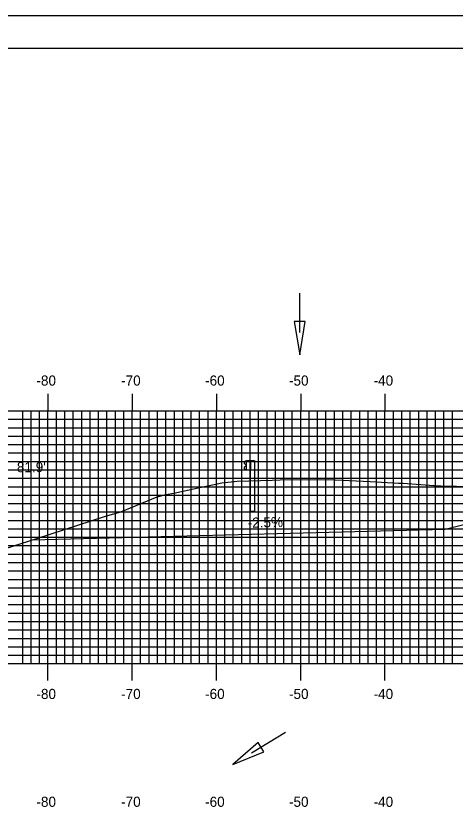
# Model space of a CAD drawing. Extents: x 1684405 to 1684749, y 461260 to 461480.
# Drawn here: x 1684487.4 to 1684539.5, y 461385.6 to 461480 of the extents above; entities that cross this region are included whole.
import ezdxf

# ---------------------------------------------------------------- set-up
doc = ezdxf.new("R2010")
doc.units = 0
for name, color, linetype in [('ANNOTATION', 7, 'Continuous'), ('BORDER', 7, 'Continuous'), ('D_Drainage_Ditch_Line', 7, 'Continuous'), ('D_Roadway_SlopeLines', 7, 'Continuous'), ('D_Text_Standard', 7, 'Continuous'), ('H_V ANNOTATION', 7, 'Continuous'), ('M_Roadway_Centerline', 7, 'Continuous'), ('MAJOR', 7, 'Continuous'), ('MINOR', 7, 'Continuous'), ('PLOT BOUNDARY', 7, 'Continuous'), ('S_Guardrail_Beam', 7, 'Continuous'), ('S_Roadway_Centerline', 7, 'Continuous')]:
    doc.layers.add(name, color=color, linetype=linetype)

msp = doc.modelspace()

# ---------------------------------------------------------------- linework, layer by layer
at = {"layer": 'BORDER'}
msp.add_lwpolyline([(1684421.603, 461266.072), (1684741.603, 461266.072), (1684741.603, 461476.072), (1684421.603, 461476.072)], close=True, dxfattribs=at)
at = {"layer": 'D_Drainage_Ditch_Line'}
for p, q in [((1684521.078, 461442.355), (1684521.078, 461447.054)), ((1684515.369, 461392.475), (1684519.377, 461394.928))]:
    msp.add_line(p, q, dxfattribs=at)
for points in [[(1684521.734, 461443.667), (1684520.422, 461443.667), (1684521.078, 461439.73)], [(1684516.831, 461392.6), (1684516.146, 461393.72), (1684513.13, 461391.105)]]:
    msp.add_lwpolyline(points, close=True, dxfattribs=at)
at = {"layer": 'D_Roadway_SlopeLines'}
for points in [[(1684553.203, 461422.694), (1684538.334, 461418.977)], [(1684538.334, 461418.977), (1684489.298, 461417.743)]]:
    msp.add_lwpolyline(points, dxfattribs=at)
at = {"layer": 'MAJOR'}
for p, q in [((1684491.203, 461435.076), (1684491.203, 461433.072)), ((1684501.203, 461435.076), (1684501.203, 461433.072)), ((1684511.203, 461435.076), (1684511.203, 461433.072)), ((1684521.203, 461435.076), (1684521.203, 461433.072)), ((1684531.203, 461435.076), (1684531.203, 461433.072)), ((1684431.203, 461433.072), (1684711.203, 461433.072)), ((1684431.203, 461433.072), (1684711.203, 461433.072)), ((1684491.203, 461403.072), (1684491.203, 461433.072)), ((1684501.203, 461403.072), (1684501.203, 461433.072)), ((1684511.203, 461403.072), (1684511.203, 461433.072)), ((1684521.203, 461403.072), (1684521.203, 461433.072)), ((1684531.203, 461403.072), (1684531.203, 461433.072)), ((1684431.203, 461428.072), (1684711.203, 461428.072)), ((1684431.203, 461423.072), (1684711.203, 461423.072)), ((1684431.203, 461418.072), (1684711.203, 461418.072)), ((1684431.203, 461413.072), (1684711.203, 461413.072)), ((1684431.203, 461408.072), (1684711.203, 461408.072)), ((1684431.203, 461403.072), (1684711.203, 461403.072)), ((1684431.203, 461403.072), (1684711.203, 461403.072)), ((1684491.203, 461401.068), (1684491.203, 461403.072)), ((1684501.203, 461401.068), (1684501.203, 461403.072)), ((1684511.203, 461401.068), (1684511.203, 461403.072)), ((1684521.203, 461401.068), (1684521.203, 461403.072)), ((1684531.203, 461401.068), (1684531.203, 461403.072))]:
    msp.add_line(p, q, dxfattribs=at)
at = {"layer": 'MINOR'}
for p, q in [((1684488.203, 461403.072), (1684488.203, 461433.072)), ((1684489.203, 461403.072), (1684489.203, 461433.072)), ((1684490.203, 461403.072), (1684490.203, 461433.072)), ((1684492.203, 461403.072), (1684492.203, 461433.072)), ((1684493.203, 461403.072), (1684493.203, 461433.072)), ((1684494.203, 461403.072), (1684494.203, 461433.072)), ((1684495.203, 461403.072), (1684495.203, 461433.072)), ((1684496.203, 461403.072), (1684496.203, 461433.072)), ((1684497.203, 461403.072), (1684497.203, 461433.072)), ((1684498.203, 461403.072), (1684498.203, 461433.072)), ((1684499.203, 461403.072), (1684499.203, 461433.072)), ((1684500.203, 461403.072), (1684500.203, 461433.072)), ((1684502.203, 461403.072), (1684502.203, 461433.072)), ((1684503.203, 461403.072), (1684503.203, 461433.072)), ((1684504.203, 461403.072), (1684504.203, 461433.072)), ((1684505.203, 461403.072), (1684505.203, 461433.072)), ((1684506.203, 461403.072), (1684506.203, 461433.072)), ((1684507.203, 461403.072), (1684507.203, 461433.072)), ((1684508.203, 461403.072), (1684508.203, 461433.072)), ((1684509.203, 461403.072), (1684509.203, 461433.072)), ((1684510.203, 461403.072), (1684510.203, 461433.072)), ((1684512.203, 461403.072), (1684512.203, 461433.072)), ((1684513.203, 461403.072), (1684513.203, 461433.072)), ((1684514.203, 461403.072), (1684514.203, 461433.072)), ((1684515.203, 461403.072), (1684515.203, 461433.072)), ((1684516.203, 461403.072), (1684516.203, 461433.072)), ((1684517.203, 461403.072), (1684517.203, 461433.072)), ((1684518.203, 461403.072), (1684518.203, 461433.072)), ((1684519.203, 461403.072), (1684519.203, 461433.072)), ((1684520.203, 461403.072), (1684520.203, 461433.072)), ((1684522.203, 461403.072), (1684522.203, 461433.072)), ((1684523.203, 461403.072), (1684523.203, 461433.072)), ((1684524.203, 461403.072), (1684524.203, 461433.072)), ((1684525.203, 461403.072), (1684525.203, 461433.072)), ((1684526.203, 461403.072), (1684526.203, 461433.072)), ((1684527.203, 461403.072), (1684527.203, 461433.072)), ((1684528.203, 461403.072), (1684528.203, 461433.072)), ((1684529.203, 461403.072), (1684529.203, 461433.072)), ((1684530.203, 461403.072), (1684530.203, 461433.072)), ((1684532.203, 461403.072), (1684532.203, 461433.072)), ((1684533.203, 461403.072), (1684533.203, 461433.072)), ((1684534.203, 461403.072), (1684534.203, 461433.072)), ((1684535.203, 461403.072), (1684535.203, 461433.072)), ((1684536.203, 461403.072), (1684536.203, 461433.072)), ((1684537.203, 461403.072), (1684537.203, 461433.072)), ((1684538.203, 461403.072), (1684538.203, 461433.072)), ((1684539.203, 461403.072), (1684539.203, 461433.072)), ((1684431.203, 461432.072), (1684711.203, 461432.072)), ((1684431.203, 461431.072), (1684711.203, 461431.072)), ((1684431.203, 461430.072), (1684711.203, 461430.072)), ((1684431.203, 461429.072), (1684711.203, 461429.072)), ((1684431.203, 461427.072), (1684711.203, 461427.072)), ((1684431.203, 461426.072), (1684711.203, 461426.072)), ((1684431.203, 461425.072), (1684711.203, 461425.072)), ((1684431.203, 461424.072), (1684711.203, 461424.072)), ((1684431.203, 461422.072), (1684711.203, 461422.072)), ((1684431.203, 461421.072), (1684711.203, 461421.072)), ((1684431.203, 461420.072), (1684711.203, 461420.072)), ((1684431.203, 461419.072), (1684711.203, 461419.072)), ((1684431.203, 461417.072), (1684711.203, 461417.072)), ((1684431.203, 461416.072), (1684711.203, 461416.072)), ((1684431.203, 461415.072), (1684711.203, 461415.072)), ((1684431.203, 461414.072), (1684711.203, 461414.072)), ((1684431.203, 461412.072), (1684711.203, 461412.072)), ((1684431.203, 461411.072), (1684711.203, 461411.072)), ((1684431.203, 461410.072), (1684711.203, 461410.072)), ((1684431.203, 461409.072), (1684711.203, 461409.072)), ((1684431.203, 461407.072), (1684711.203, 461407.072)), ((1684431.203, 461406.072), (1684711.203, 461406.072)), ((1684431.203, 461405.072), (1684711.203, 461405.072)), ((1684431.203, 461404.072), (1684711.203, 461404.072))]:
    msp.add_line(p, q, dxfattribs=at)
at = {"layer": 'PLOT BOUNDARY'}
msp.add_lwpolyline([(1684405.417, 461259.954), (1684745.417, 461259.954), (1684745.417, 461479.954), (1684405.417, 461479.954)], close=True, dxfattribs=at)
at = {"layer": 'S_Guardrail_Beam'}
for p, q in [((1684514.651, 461427.09), (1684514.507, 461426.99)), ((1684514.651, 461427.09), (1684514.507, 461426.99)), ((1684514.507, 461426.847), (1684514.703, 461426.71)), ((1684514.507, 461426.847), (1684514.703, 461426.71)), ((1684514.703, 461426.491), (1684514.507, 461426.354)), ((1684514.703, 461426.491), (1684514.507, 461426.354)), ((1684514.75, 461427.111), (1684514.668, 461427.096)), ((1684514.75, 461427.111), (1684514.668, 461427.096)), ((1684514.736, 461426.646), (1684514.736, 461426.555)), ((1684514.736, 461426.646), (1684514.736, 461426.555)), ((1684514.75, 461427.184), (1684515.239, 461427.184)), ((1684514.75, 461426.017), (1684514.75, 461427.184)), ((1684514.75, 461427.184), (1684515.239, 461427.184)), ((1684514.75, 461426.017), (1684514.75, 461427.184)), ((1684515.239, 461427.184), (1684515.731, 461427.184)), ((1684515.239, 461427.184), (1684515.239, 461426.017)), ((1684515.239, 461427.184), (1684515.731, 461427.184)), ((1684515.239, 461427.184), (1684515.239, 461426.017)), ((1684515.731, 461427.184), (1684515.731, 461421.184)), ((1684515.731, 461427.184), (1684515.731, 461421.184)), ((1684514.507, 461426.211), (1684514.651, 461426.111)), ((1684514.507, 461426.211), (1684514.651, 461426.111)), ((1684514.668, 461426.104), (1684514.75, 461426.09)), ((1684514.668, 461426.104), (1684514.75, 461426.09)), ((1684515.239, 461426.017), (1684514.75, 461426.017)), ((1684515.239, 461426.017), (1684514.75, 461426.017)), ((1684515.239, 461421.184), (1684515.239, 461426.017)), ((1684515.239, 461421.184), (1684515.239, 461426.017)), ((1684515.239, 461421.184), (1684515.731, 461421.184)), ((1684515.239, 461421.184), (1684515.731, 461421.184))]:
    msp.add_line(p, q, dxfattribs=at)
for centre, major_axis, start_param, end_param in [((1684514.558, 461426.918), (-0.0877, 0), 5.323254, 7.243116), ((1684514.558, 461426.918), (-0.0877, 0), 5.323254, 7.243116), ((1684514.558, 461426.283), (-0.0877, 0), 5.323254, 7.243116), ((1684514.558, 461426.283), (-0.0877, 0), 5.323254, 7.243116), ((1684514.675, 461427.056), (-0.0417, 0), 4.886922, 5.323254), ((1684514.675, 461427.056), (-0.0417, 0), 4.886922, 5.323254), ((1684514.658, 461426.646), (0.0789, 0), 0, 0.959931), ((1684514.658, 461426.646), (0.0789, 0), 0, 0.959931), ((1684514.658, 461426.555), (0.0789, 0), 5.323254, 6.283185), ((1684514.658, 461426.555), (0.0789, 0), 5.323254, 6.283185), ((1684514.675, 461426.145), (-0.0417, 0), 0.959931, 1.396263), ((1684514.675, 461426.145), (-0.0417, 0), 0.959931, 1.396263)]:
    msp.add_ellipse(centre, major_axis=major_axis, ratio=0.995501, start_param=start_param, end_param=end_param, dxfattribs=at)
at = {"layer": 'S_Roadway_Centerline'}
msp.add_lwpolyline([(1684479.557, 461414.654), (1684489.875, 461417.926), (1684498.02, 461420.569), (1684499.837, 461421.101), (1684504.164, 461422.876), (1684505.245, 461423.137), (1684506.127, 461423.306), (1684509.038, 461423.917), (1684510.918, 461424.319), (1684511.855, 461424.542), (1684513.655, 461424.71), (1684517.797, 461424.862), (1684518.745, 461424.88), (1684524.468, 461424.916), (1684529.427, 461424.678), (1684532.825, 461424.486), (1684533.349, 461424.474), (1684537.018, 461424.221), (1684537.053, 461424.219), (1684537.635, 461424.182), (1684537.826, 461424.176), (1684541.556, 461424.091)], dxfattribs=at)

# ---------------------------------------------------------------- texts
at = {"layer": 'ANNOTATION'}
msp.add_text('-2.5%', height=1.2, rotation=1.44148, dxfattribs=at).set_placement((1684514.923, 461419.189))
at = {"layer": 'D_Text_Standard'}
msp.add_text("81.9'", height=1.2, dxfattribs=at).set_placement((1684487.516, 461425.796))
at = {"layer": 'H_V ANNOTATION'}
for s, p in [('-80', (1684489.833, 461436.072)), ('-70', (1684499.886, 461436.072)), ('-60', (1684509.855, 461436.072)), ('-50', (1684519.812, 461436.072)), ('-40', (1684529.855, 461436.072)), ('-80', (1684489.833, 461398.872)), ('-70', (1684499.886, 461398.872)), ('-60', (1684509.855, 461398.872)), ('-50', (1684519.812, 461398.872)), ('-40', (1684529.855, 461398.872)), ('-80', (1684489.833, 461386.072)), ('-70', (1684499.886, 461386.072)), ('-60', (1684509.855, 461386.072)), ('-50', (1684519.812, 461386.072)), ('-40', (1684529.855, 461386.072))]:
    msp.add_text(s, height=1.2, dxfattribs=at).set_placement(p)
at = {"layer": 'M_Roadway_Centerline'}
for s, p in [('C', (1684533.344, 461424.474)), ('L', (1684533.349, 461424.466))]:
    msp.add_text(s, height=0.0146, dxfattribs=at).set_placement(p)

doc.saveas('drawing.dxf')
